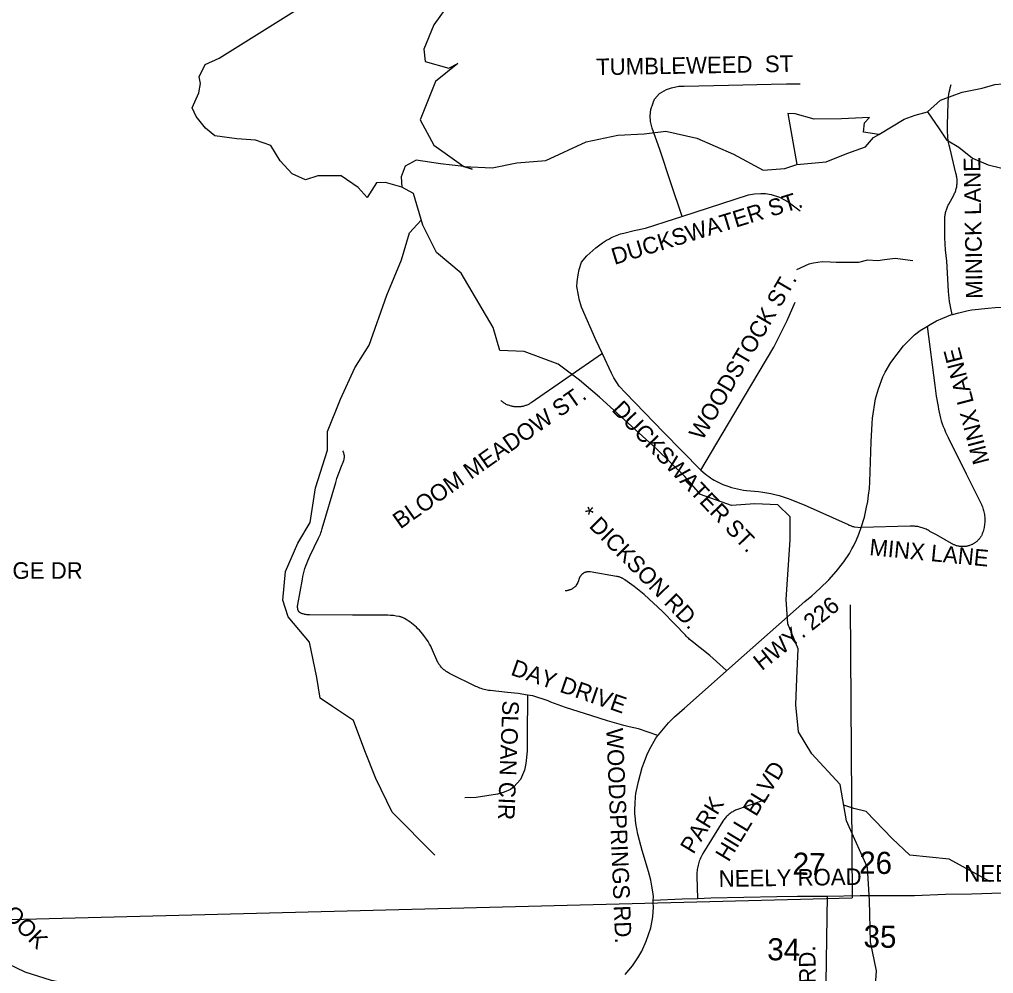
# Model space of a CAD drawing. Extents: x 1670563 to 1761545, y 515755 to 578944.
# Drawn here: x 1679340 to 1683746, y 538317 to 542631 of the extents above; entities that cross this region are included whole.
import ezdxf

# ---------------------------------------------------------------- set-up
doc = ezdxf.new("R2010")
doc.units = 0
for name, color, linetype in [('5_sectionlines', 7, 'Continuous'), ('62_text', 7, 'Continuous'), ('SHP_LINE', 7, 'Continuous'), ('STREETCL', 7, 'Continuous'), ('STRNAMES', 7, 'Continuous')]:
    doc.layers.add(name, color=color, linetype=linetype)

msp = doc.modelspace()

# ---------------------------------------------------------------- linework, layer by layer
at = {"layer": '5_sectionlines'}
for p in [(1683097.4, 539985.1), (1677796.8, 538521.9)]:
    msp.add_line(p, (1683105.9, 538659.8), dxfattribs=at)
at = {"layer": 'SHP_LINE'}
for points in [[(1681069, 541873), (1680995, 541894), (1680955, 541892), (1680913, 541826), (1680871, 541872), (1680795, 541924), (1680689, 541924), (1680633, 541906), (1680573, 541934), (1680519, 541992), (1680477, 542062), (1680407, 542086), (1680323, 542092), (1680223, 542106), (1680181, 542140), (1680139, 542192), (1680121, 542232), (1680151, 542300), (1680159, 542342), (1680153, 542372), (1680179, 542428), (1680243, 542456), (1681080, 542981)], [(1681276, 542693), (1681214, 542607), (1681168, 542497), (1681174, 542441), (1681282, 542411), (1681322, 542433), (1681222, 542351), (1681152, 542177), (1681214, 542063), (1681276, 542019), (1681350, 541966), (1681244, 541978), (1681134, 541995), (1681084, 541968), (1681066, 541920), (1681069, 541873)], [(1683447, 542214), (1683506, 542266), (1683570, 542290), (1683604, 542303), (1683694, 542321), (1683752, 542337), (1683786, 542340), (1683841, 542370), (1683875, 542429), (1683912, 542490), (1683940, 542540), (1683971, 542577), (1684011, 542613)], [(1682816, 542206), (1682856, 541976), (1682988, 541988), (1683082, 542026), (1683166, 542056), (1683203, 542098), (1683227, 542112), (1683158, 542122), (1683162, 542164), (1683184, 542188), (1683058, 542182), (1682934, 542180), (1682848, 542204), (1682816, 542206)], [(1683227, 542112), (1683342, 542180), (1683392, 542198), (1683447, 542214)], [(1683447, 542214), (1683500, 542137), (1683533, 542087), (1683589, 542054), (1683650, 542004), (1683721, 541974), (1683777, 541961), (1683838, 541955), (1683995, 541875), (1684060, 541807), (1684122, 541758), (1684211, 541718), (1684291, 541690), (1684383, 541657)], [(1681350, 541966), (1681388, 541954), (1681350, 541966), (1681478, 541961), (1681590, 541983), (1681720, 541993), (1681903, 542078), (1682047, 542108), (1682165, 542114), (1682263, 542126), (1682403, 542094), (1682570, 542022), (1682704, 541950), (1682802, 541958), (1682856, 541976)], [(1683212, 538264), (1683217, 538329), (1683189, 538460), (1683184, 538648), (1683175, 538797), (1683118, 538924), (1683080, 539008), (1683052, 539172), (1682924, 539310), (1682864, 539410), (1682852, 539532), (1682856, 539652), (1682862, 539786), (1682816, 539898), (1682808, 540009), (1682826, 540279), (1682826, 540383), (1682770, 540437), (1682666, 540441), (1682560, 540433), (1682420, 540483), (1682350, 540565), (1682222, 540689), (1681963, 540924), (1681873, 541000), (1681777, 541072), (1681623, 541130), (1681513, 541134), (1681482, 541239), (1681338, 541485), (1681226, 541577), (1681164, 541701), (1681122, 541845), (1681069, 541873)], [(1681218, 538853), (1681026, 539047), (1680952, 539199), (1680902, 539325), (1680851, 539462), (1680755, 539524), (1680699, 539562), (1680685, 539656), (1680651, 539816), (1680555, 539930), (1680531, 540005), (1680543, 540135), (1680599, 540263), (1680655, 540357), (1680679, 540513), (1680733, 540684), (1680733, 540768), (1680791, 540914), (1680857, 541056), (1680922, 541158), (1681002, 541385), (1681068, 541545), (1681104, 541667), (1681157, 541724)], [(1683380, 541540), (1683301, 541550), (1683252, 541544), (1683223, 541540), (1683176, 541543), (1683135, 541532), (1683064, 541532), (1683034, 541532), (1683007, 541534), (1682970, 541535), (1682932, 541529), (1682910, 541525), (1682855, 541500)], [(1680210, 537900), (1680101, 538009), (1679998, 538040), (1679920, 538045), (1679823, 538143), (1679747, 538185), (1679588, 538265), (1679485, 538285), (1679365, 538324), (1679245, 538380), (1679175, 538427), (1679142, 538491), (1679100, 538513), (1678966, 538458), (1678919, 538405), (1678858, 538410), (1678818, 538527), (1678699, 538692), (1678634, 538784), (1678598, 538892), (1678598, 538990), (1678608, 539076)], [(1683732, 538732), (1683545, 538835), (1683367, 538853), (1683287, 538928), (1683170, 539050), (1683114, 539064), (1683068, 539079)]]:
    msp.add_lwpolyline(points, dxfattribs=at)
at = {"layer": 'STREETCL'}
for points in [[(1682336.9, 541740.5), (1682286.6, 541892.4), (1682236.1, 542044), (1682201.5, 542140.2), (1682194.4, 542170.5), (1682193.2, 542195.3), (1682196, 542224.8), (1682205.4, 542254.7), (1682212.3, 542271), (1682235.3, 542297.1), (1682266.2, 542314.9), (1682289.5, 542322.5), (1682321.6, 542329.7), (1682346.1, 542330), (1682547.1, 542334.1), (1682739.7, 542339.1), (1682808.5, 542340.1), (1682871.2, 542340.8)], [(1683559.3, 541297.2), (1683552.8, 541326.1), (1683549.6, 541341), (1683547, 541355.9), (1683544.8, 541370.9), (1683543.2, 541386), (1683541.9, 541401.1), (1683535.8, 541512.3), (1683533.9, 541538.1), (1683531.2, 541563.9), (1683528.3, 541590.5), (1683526.3, 541617.2), (1683525, 541643.9), (1683525.8, 541731.3), (1683525.9, 541735.9), (1683526.2, 541740.4), (1683526.6, 541744.9), (1683527.2, 541749.3), (1683528, 541753.8), (1683528.8, 541758.2), (1683529.9, 541762.6), (1683531.1, 541767), (1683532.4, 541771.3), (1683533.9, 541775.6), (1683535.6, 541779.8), (1683537.3, 541783.9), (1683539.3, 541788), (1683541.3, 541792.1), (1683543.5, 541796), (1683565.9, 541837.6), (1683567.9, 541841.5), (1683569.8, 541845.5), (1683571.5, 541849.5), (1683573.1, 541853.7), (1683574.6, 541857.8), (1683575.9, 541862), (1683577.1, 541866.3), (1683578.2, 541870.6), (1683579.1, 541874.9), (1683579.8, 541879.3), (1683580.4, 541883.6), (1683580.9, 541888), (1683581.1, 541892.4), (1683581.3, 541896.9), (1683581.3, 541901.3), (1683581.1, 541905.7), (1683580.8, 541910.1), (1683580.4, 541914.5), (1683579.8, 541918.9), (1683579, 541923.2), (1683578.1, 541927.5), (1683577.1, 541931.8), (1683575.9, 541936.1), (1683547.4, 542052.2), (1683544.8, 542063.4), (1683542.7, 542074.6), (1683540.9, 542086), (1683539.5, 542097.3), (1683538.4, 542108.7), (1683537.8, 542120.2), (1683537.5, 542131.7), (1683537.6, 542143.1), (1683538.1, 542154.6), (1683540.5, 542253.9), (1683540.8, 542263.6), (1683541.5, 542273.4), (1683542.5, 542283.1), (1683543.9, 542292.8), (1683545.5, 542302.5), (1683547.4, 542312.1), (1683549.7, 542321.6), (1683554.3, 542337.4)], [(1682335.6, 541740), (1682636.7, 541838.1), (1682664.8, 541843.6), (1682692.9, 541845.2), (1682714, 541844.4), (1682740.6, 541839.7), (1682777.2, 541828), (1682816.2, 541806.1), (1682871.8, 541766)], [(1681976.7, 541119.4), (1681947.4, 541182.3), (1681881.8, 541329.8), (1681870.7, 541367.1), (1681868.4, 541384.2), (1681861.4, 541423.3), (1681862.2, 541445.1), (1681866.1, 541476.3), (1681871.5, 541501.3), (1681882.5, 541533.3), (1681905.3, 541562.7), (1681946.8, 541598.9), (1681977.6, 541621), (1681986.5, 541627.1), (1681995.5, 541632.9), (1682004.8, 541638.4), (1682014.2, 541643.7), (1682021.3, 541647.3), (1682028.6, 541650.7), (1682035.9, 541653.8), (1682043.3, 541656.7), (1682050.9, 541659.3), (1682058.5, 541661.7), (1682066.2, 541663.8), (1682073.9, 541665.6), (1682120.6, 541677), (1682171.9, 541688), (1682302.6, 541729.3), (1682335.6, 541740)], [(1682421.2, 540593.8), (1682619.2, 540926.7), (1682752.2, 541149.9), (1682812, 541269.5), (1682848.9, 541352.9)], [(1683560.3, 541297.5), (1683588.5, 541305.2), (1683631.7, 541315.5), (1683646.9, 541318.3), (1683721.4, 541326.5), (1683753.7, 541328.9), (1683813.5, 541332.3), (1683871.5, 541335), (1683938.4, 541337.6), (1684052.2, 541342.8), (1684091.8, 541345.5), (1684131.3, 541349.3)], [(1683446.9, 541245.2), (1683458.7, 541252.4), (1683487.2, 541268.9), (1683516.6, 541281), (1683551.9, 541295.2), (1683560.3, 541297.5)], [(1683147.1, 540334.1), (1683161.5, 540380.3), (1683171.7, 540426.6), (1683177.1, 540451.5), (1683180.6, 540480.5), (1683184.3, 540509.9), (1683186.1, 540541.1), (1683192.3, 540721), (1683196.8, 540804.8), (1683199, 540827.9), (1683211.5, 540915.7), (1683224.9, 540961.1), (1683245, 541015), (1683256.1, 541036), (1683281.1, 541079.6), (1683338.6, 541155.4), (1683366.6, 541184.3), (1683388.5, 541204.8), (1683414.1, 541224.8), (1683446.9, 541245.2)], [(1683445.3, 541244.2), (1683480.7, 540975.7), (1683487, 540928.7), (1683494.9, 540881.9), (1683496.9, 540868.6), (1683499.4, 540855.3), (1683502.3, 540842.1), (1683505.6, 540829), (1683509.4, 540816.1), (1683513.7, 540803.2), (1683518.4, 540790.6), (1683523.5, 540778.1), (1683529, 540765.7), (1683535, 540753.6), (1683541.3, 540741.7), (1683622.6, 540577.4), (1683688.5, 540443.7), (1683691, 540438.4), (1683693.4, 540432.9), (1683695.5, 540427.3), (1683697.5, 540421.7), (1683699.3, 540416), (1683700.8, 540410.3), (1683702.2, 540404.5), (1683703.4, 540398.6), (1683704.4, 540392.8), (1683705.2, 540386.8), (1683705.7, 540380.9), (1683706.1, 540375), (1683706.3, 540369), (1683706.2, 540363.1), (1683706, 540357.1), (1683705.5, 540351.2), (1683704.8, 540345.2), (1683704, 540339.3), (1683702.9, 540333.5), (1683701.6, 540327.7), (1683700.2, 540321.9), (1683698.5, 540316.2), (1683696.6, 540310.5), (1683694.6, 540304.9), (1683692.3, 540299.4), (1683690.7, 540296.5), (1683689, 540293.6), (1683687.2, 540290.8), (1683685.3, 540288.1), (1683683.3, 540285.4), (1683681.2, 540282.8), (1683679.1, 540280.2), (1683676.8, 540277.8), (1683674.5, 540275.4), (1683672, 540273.1), (1683669.5, 540270.9), (1683667, 540268.8), (1683664.3, 540266.8), (1683661.6, 540264.8), (1683658.8, 540263), (1683656, 540261.2), (1683653.1, 540259.6), (1683650.1, 540258), (1683647.1, 540256.6), (1683644.1, 540255.2), (1683641, 540254), (1683637.8, 540252.9), (1683634.7, 540251.8), (1683631.5, 540250.9), (1683628.2, 540250.1), (1683625, 540249.4), (1683621.7, 540248.9), (1683618.4, 540248.4), (1683615.1, 540248), (1683611.7, 540247.8), (1683608.4, 540247.7), (1683605.1, 540247.7), (1683601.7, 540247.8), (1683598.4, 540248), (1683595.1, 540248.4), (1683591.8, 540248.8), (1683588.5, 540249.4), (1683585.2, 540250), (1683582, 540250.8), (1683578.8, 540251.7), (1683575.6, 540252.7), (1683572.4, 540253.9), (1683569.3, 540255.1), (1683566.3, 540256.4), (1683487.7, 540300.4), (1683458.1, 540316.2), (1683453.9, 540318.9), (1683449.7, 540321.5), (1683445.3, 540323.9), (1683440.9, 540326.1), (1683436.3, 540328.2), (1683431.7, 540330.1), (1683427.1, 540331.8), (1683422.4, 540333.4), (1683417.6, 540334.8), (1683412.8, 540336.1), (1683407.9, 540337.2), (1683403, 540338.1), (1683398.1, 540338.8), (1683393.2, 540339.4), (1683388.2, 540339.8), (1683383.2, 540340), (1683378.3, 540340.1), (1683373.3, 540340), (1683368.3, 540339.7), (1683147.1, 540334.1)], [(1681976.2, 541120.4), (1681654.2, 540898.2), (1681651.1, 540896.2), (1681648, 540894.3), (1681644.9, 540892.5), (1681641.7, 540890.8), (1681638.4, 540889.2), (1681635.1, 540887.7), (1681631.7, 540886.3), (1681628.3, 540885.1), (1681624.8, 540883.9), (1681621.3, 540882.9), (1681617.8, 540882), (1681614.2, 540881.2), (1681610.6, 540880.6), (1681607, 540880), (1681603.4, 540879.6), (1681599.8, 540879.3), (1681596.2, 540879.1), (1681592.5, 540879.1), (1681588.9, 540879.2), (1681585.2, 540879.4), (1681581.6, 540879.7), (1681577.8, 540880.1), (1681574.1, 540880.6), (1681570.4, 540881.3), (1681566.7, 540882.1), (1681563, 540883), (1681559.3, 540884.1), (1681555.7, 540885.3), (1681552.2, 540886.6), (1681548.7, 540888), (1681545.2, 540889.5), (1681541.8, 540891.1), (1681538.4, 540892.9), (1681535.1, 540894.8), (1681531.9, 540896.8), (1681528.8, 540898.9), (1681525.7, 540901.1), (1681522.7, 540903.4), (1681519.7, 540905.8), (1681516.9, 540908.3)], [(1682421.2, 540593.8), (1682252.1, 540765.4), (1682081.1, 540942.8), (1682052.2, 540974), (1682028.8, 541011.5), (1682017.1, 541032.6), (1681976.7, 541119.4)], [(1681637.3, 539576.7), (1681596.1, 539583.7), (1681546.6, 539588.3), (1681468.7, 539596.8), (1681461.9, 539597.7), (1681455.2, 539598.8), (1681448.5, 539600.2), (1681441.8, 539601.8), (1681435.2, 539603.6), (1681428.7, 539605.6), (1681422.2, 539607.9), (1681415.8, 539610.3), (1681409.5, 539613), (1681403.3, 539615.9), (1681288.4, 539672.7), (1681284.6, 539674.6), (1681280.8, 539676.6), (1681277.1, 539678.7), (1681273.4, 539680.9), (1681269.9, 539683.3), (1681266.4, 539685.8), (1681263, 539688.4), (1681259.7, 539691.2), (1681256.5, 539694), (1681253.4, 539696.9), (1681250.4, 539700), (1681247.5, 539703.2), (1681244.7, 539706.4), (1681242, 539709.7), (1681239.5, 539713.2), (1681237, 539716.7), (1681234.7, 539720.3), (1681232.5, 539724), (1681203.8, 539789.3), (1681201.8, 539793.8), (1681199.6, 539798.2), (1681197.3, 539802.6), (1681194.9, 539806.8), (1681187.7, 539818.3), (1681180.1, 539829.6), (1681172.2, 539840.6), (1681164, 539851.4), (1681155.4, 539862), (1681148.9, 539869.2), (1681142.2, 539876.1), (1681135.3, 539882.8), (1681128.1, 539889.3), (1681120.7, 539895.6), (1681113.1, 539901.6), (1681105.3, 539907.3), (1681097.4, 539912.8), (1681089.2, 539918), (1681080.9, 539923), (1681078.3, 539924.3), (1681075.5, 539925.6), (1681072.8, 539926.8), (1681070, 539927.9), (1681067.2, 539928.9), (1681064.3, 539929.8), (1681061.4, 539930.6), (1681058.5, 539931.3), (1681055.6, 539931.8), (1681043.3, 539933.9), (1681030.9, 539935.5), (1681018.5, 539936.7), (1681006.1, 539937.4), (1680993.6, 539937.7), (1680846.7, 539937.4), (1680651.8, 539938.6), (1680647.6, 539938.8), (1680643.4, 539939.2), (1680639.2, 539939.7), (1680635, 539940.4), (1680630.8, 539941.2), (1680626.7, 539942.1), (1680622.6, 539943.2), (1680618.6, 539944.5), (1680614.6, 539945.8), (1680613.8, 539946.1), (1680613.1, 539946.4), (1680612.3, 539946.8), (1680611.6, 539947.1), (1680610.8, 539947.5), (1680610.1, 539947.9), (1680609.4, 539948.4), (1680608.7, 539948.8), (1680608, 539949.3), (1680607.4, 539949.8), (1680606.8, 539950.4), (1680606.1, 539950.9), (1680605.5, 539951.5), (1680605, 539952.1), (1680604.4, 539952.7), (1680603.9, 539953.3), (1680603.3, 539954), (1680602.8, 539954.6), (1680602.4, 539955.3), (1680601.9, 539956), (1680601.5, 539956.7), (1680601.1, 539957.5), (1680600.7, 539958.2), (1680600.4, 539958.9), (1680600, 539959.7), (1680599.7, 539960.5), (1680599.5, 539961.3), (1680599.2, 539962.1), (1680598.8, 539964.4), (1680598.4, 539966.8), (1680598.1, 539969.1), (1680597.9, 539971.5), (1680597.8, 539973.9), (1680597.7, 539976.3), (1680597.8, 539978.6), (1680597.9, 539981), (1680598.1, 539983.4), (1680598.3, 539985.8), (1680619.3, 540100.9), (1680621.6, 540112.9), (1680624.3, 540124.9), (1680627.4, 540136.7), (1680630.8, 540148.5), (1680634.6, 540160.1), (1680638.8, 540171.6), (1680643.4, 540183), (1680648.3, 540194.2), (1680653.5, 540205.2), (1680692.4, 540286.3), (1680695.4, 540292.2), (1680698.2, 540298.2), (1680700.8, 540304.4), (1680703.2, 540310.6), (1680705.4, 540316.9), (1680707.4, 540323.3), (1680709.1, 540329.7), (1680770.4, 540538.3), (1680775.2, 540555), (1680780.6, 540571.6), (1680786.6, 540587.9), (1680793.1, 540604), (1680806.6, 540637.5), (1680807.2, 540639.2), (1680807.6, 540641), (1680808.1, 540642.8), (1680808.4, 540644.6), (1680808.7, 540646.4), (1680809, 540648.2), (1680809.1, 540650.1), (1680809.3, 540651.9), (1680809.3, 540653.7), (1680809.3, 540655.6), (1680809.2, 540657.4), (1680809.1, 540659.2), (1680808.9, 540661.1), (1680808.6, 540662.9), (1680808.3, 540664.7), (1680807.9, 540666.5), (1680807.5, 540668.3), (1680807, 540670), (1680806.4, 540671.8), (1680805.8, 540673.5), (1680805.1, 540675.2), (1680804.4, 540676.9), (1680803.6, 540678.6), (1680802.8, 540680.2)], [(1682421.2, 540593.8), (1682441.8, 540576.6), (1682449.6, 540570.4), (1682457.5, 540564.4), (1682465.7, 540558.7), (1682474, 540553.3), (1682482.5, 540548.2), (1682491.2, 540543.4), (1682500.1, 540538.9), (1682509.1, 540534.7), (1682521.8, 540529.3), (1682534.8, 540524.3), (1682547.9, 540519.8), (1682561.1, 540515.6), (1682574.5, 540512), (1682588, 540508.7), (1682601.6, 540506), (1682615.2, 540503.6), (1682629, 540501.8), (1682663.9, 540498), (1682682.7, 540496.3), (1682701.5, 540494), (1682720.2, 540491.1), (1682738.8, 540487.5), (1682757.2, 540483.4), (1682775.6, 540478.6), (1682793.7, 540473.2), (1682811.7, 540467.3), (1682829.4, 540460.7), (1682846.9, 540453.6), (1682889.7, 540436.1), (1683088, 540347), (1683091.3, 540345.4), (1683094.6, 540344), (1683098, 540342.6), (1683101.4, 540341.4), (1683104.9, 540340.2), (1683108.4, 540339.2), (1683111.9, 540338.3), (1683115.5, 540337.5), (1683147.1, 540334.1)], [(1682227.2, 539393), (1682229.6, 539396.2), (1682275.5, 539451), (1682302.2, 539477.8), (1682347.2, 539517.9), (1682617.2, 539757.1), (1682892.6, 539998.9), (1682923.3, 540025.2), (1682962, 540060), (1683001.3, 540097.4), (1683034.2, 540134.8), (1683069, 540178.9), (1683093.5, 540217.2), (1683105.1, 540237.3), (1683111.6, 540249.3), (1683125.8, 540277.8), (1683136.5, 540304.1), (1683147.1, 540334.1)], [(1682538.3, 539687.2), (1682461.8, 539755.1), (1682374.9, 539824.8), (1682370.9, 539828.1), (1682367, 539831.5), (1682363.2, 539835.1), (1682359.6, 539838.8), (1682356.1, 539842.6), (1682352.8, 539846.6), (1682304.7, 539897.5), (1682247.8, 539954.4), (1682166.1, 540031.5), (1682120.7, 540067.9), (1682078.2, 540097.4), (1682076.1, 540099), (1682074, 540100.5), (1682071.8, 540101.9), (1682069.6, 540103.2), (1682067.3, 540104.5), (1682065, 540105.7), (1682062.6, 540106.8), (1682060.2, 540107.9), (1682057.8, 540108.8), (1682055.3, 540109.7), (1682052.9, 540110.5), (1682050.3, 540111.2), (1682047.8, 540111.8), (1682045.3, 540112.4), (1682042.7, 540112.8), (1682040.1, 540113.2), (1681921.7, 540134), (1681920, 540134.1), (1681918.4, 540134.3), (1681916.8, 540134.3), (1681915.1, 540134.3), (1681913.5, 540134.3), (1681911.8, 540134.2), (1681910.2, 540134), (1681908.6, 540133.8), (1681907, 540133.5), (1681905.4, 540133.2), (1681903.8, 540132.8), (1681902.2, 540132.4), (1681900.6, 540131.9), (1681899.1, 540131.3), (1681897.6, 540130.7), (1681896.1, 540130.1), (1681894.6, 540129.4), (1681893.1, 540128.6), (1681891.7, 540127.8), (1681890.3, 540127), (1681888.9, 540126.1), (1681887.6, 540125.1), (1681886.3, 540124.1), (1681885, 540123.1), (1681883.8, 540122), (1681882.6, 540120.9), (1681881.4, 540119.7), (1681880.3, 540118.5), (1681879.3, 540117.3), (1681878.2, 540116), (1681877.3, 540114.7), (1681876.3, 540113.3), (1681875.4, 540111.9), (1681874.6, 540110.5), (1681873.8, 540109.1), (1681873.1, 540107.6), (1681872.4, 540106.1), (1681871.7, 540104.6), (1681871.1, 540103.1), (1681870.6, 540101.6), (1681870.1, 540100), (1681867.7, 540093.6), (1681864.7, 540086), (1681861.5, 540078.4), (1681854, 540066.9), (1681852.1, 540065.2), (1681850.2, 540063.6), (1681848.2, 540062.1), (1681846.1, 540060.6), (1681844, 540059.2), (1681841.9, 540057.9), (1681839.7, 540056.7), (1681837.5, 540055.5), (1681835.3, 540054.4), (1681833, 540053.4), (1681830.6, 540052.4), (1681828.3, 540051.6), (1681825.9, 540050.8), (1681823.5, 540050.1), (1681821.1, 540049.5), (1681818.6, 540048.9), (1681816.2, 540048.5), (1681813.7, 540048.1), (1681811.2, 540047.8), (1681808.7, 540047.6)], [(1681637.3, 539576.7), (1681636.3, 539390.4), (1681635.4, 539323.5), (1681630.3, 539267.7), (1681624.1, 539236.6), (1681605.5, 539194), (1681575.5, 539161.3), (1681560.2, 539150), (1681531.7, 539136.8), (1681501.5, 539127.8), (1681404.8, 539113.8), (1681353.4, 539111.6)], [(1682227.2, 539393), (1682139.8, 539423), (1682097.3, 539432.7), (1682074, 539438.9), (1681999.5, 539460.3), (1681928, 539483.2), (1681809.7, 539519.7), (1681742.8, 539544.8), (1681731.5, 539550.3), (1681662.4, 539572.4), (1681637.3, 539576.7)], [(1682206.7, 538648.7), (1682206.9, 538664.8), (1682205.6, 538677.7), (1682200.3, 538711.6), (1682195.4, 538739.6), (1682185.5, 538778.8), (1682181.1, 538793.1), (1682156.9, 538873.3), (1682144, 538919.1), (1682136.9, 538947.7), (1682128.4, 538996.2), (1682124.4, 539030.5), (1682123.5, 539037.6), (1682123, 539056.8), (1682124.4, 539086.6), (1682126.6, 539116.9), (1682128.4, 539131.2), (1682139.1, 539185.5), (1682156.9, 539249.2), (1682166.7, 539275.5), (1682177.5, 539304.5), (1682189.9, 539330.3), (1682218.5, 539381.1), (1682227.2, 539393)], [(1682720.8, 539106), (1682591.5, 539061), (1682587.1, 539059.4), (1682582.7, 539057.6), (1682578.4, 539055.6), (1682574.2, 539053.6), (1682570, 539051.3), (1682565.9, 539049), (1682561.9, 539046.5), (1682558, 539043.8), (1682554.1, 539041), (1682550.4, 539038.1), (1682546.8, 539035.1), (1682543.3, 539031.9), (1682539.9, 539028.7), (1682536.6, 539025.3), (1682533.4, 539021.8), (1682530.3, 539018.2), (1682527.4, 539014.4), (1682524.6, 539010.6), (1682521.9, 539006.7), (1682431.1, 538859.3), (1682427.8, 538853.8), (1682424.8, 538848.2), (1682421.9, 538842.6), (1682419.3, 538836.8), (1682416.8, 538830.9), (1682414.6, 538824.9), (1682412.5, 538818.9), (1682410.7, 538812.8), (1682409.1, 538806.6), (1682407.7, 538800.4), (1682406.5, 538794.1), (1682405.6, 538787.8), (1682404.9, 538781.5), (1682404.3, 538775.2), (1682404.1, 538768.8), (1682404, 538762.4), (1682404.1, 538756.1), (1682406.3, 538656.7)], [(1682206.7, 538648.7), (1682337.8, 538654.3), (1682406.3, 538656.7)], [(1682406.3, 538656.7), (1682467.3, 538658.8), (1682765.8, 538665.6), (1682859.4, 538666.6), (1682992.5, 538667.8), (1682993.4, 538667.8)], [(1682993.4, 538667.8), (1682990.2, 538476.3), (1682987.8, 538273.8), (1682985.5, 538015), (1682984.6, 537755.7), (1682979.6, 537517.9)], [(1682993.4, 538667.8), (1683141.8, 538670.2), (1683252.6, 538670.7), (1683388.7, 538670.6), (1683529, 538676), (1683645.4, 538678), (1683784.6, 538682.4), (1683952.7, 538686.6), (1684117.4, 538689), (1684332.9, 538692.3), (1684474.9, 538696.5), (1684492.4, 538697.4)], [(1682078.8, 538313.5), (1682112.5, 538351.7), (1682136.9, 538388.2), (1682154.3, 538418.8), (1682174.1, 538462.9), (1682194.8, 538523.2), (1682203.9, 538573.7), (1682207.4, 538618), (1682206.5, 538638.1), (1682206.7, 538648.7)]]:
    msp.add_lwpolyline(points, dxfattribs=at)

# ---------------------------------------------------------------- texts
at = {"layer": '62_text'}
for s, rotation, p in [('27', 358.644, (1682835.6, 538764.7)), ('26', 359.2136, (1683137.4, 538769.2)), ('35', 358.9328, (1683157, 538435.5)), ('34', 358.932, (1682721.5, 538377.7))]:
    msp.add_text(s, height=100, rotation=rotation, dxfattribs=at).set_placement(p)
at = {"layer": 'STRNAMES'}
for s, rotation, p in [('TUMBLEWEED  ST', 1, (1681948.7, 542379.2)), ('MINICK LANE', 90.9896, (1683696.5, 541368.9)), ('DUCKSWATER ST.', 17.0725, (1682031, 541521.2)), ('WOODSTOCK ST.', 59.6729, (1682428.6, 540723.6)), ('MINX LANE', 104.6907, (1683728, 540630.7)), ('BLOOM MEADOW ST.', 35.028, (1681062.2, 540325.2)), ('DUCKSWATER ST.', 313.653, (1682015, 540864)), ('* DICKSON RD. ', 314.3613, (1681865.5, 540386)), ('MINX LANE', 354.4555, (1683182, 540209.4)), ('HWY. 226', 38.5069, (1682697.4, 539684.1)), ('DAY DRIVE', 340.8514, (1681557.8, 539669)), ('SLOAN CIR', 267.7542, (1681524.7, 539553)), ('WOODSPRINGS RD.', 272.4044, (1681993.8, 539425.5)), ('HILL BLVD', 58.7757, (1682547.3, 538818.2)), ('PARK', 58.7757, (1682388.2, 538853.2)), ('INNISBROOK', 314.9807, (1678976, 538867.7)), ('NEELY ROAD', 0.8296, (1682503, 538708.8)), ('NEELY RD.', 359.9529, (1683613.6, 538732.5)), ('ROSELEE RD.', 90.7196, (1682948.2, 537770.2))]:
    msp.add_text(s, height=75, rotation=rotation, dxfattribs=at).set_placement(p)
msp.add_text('VINTAGE DR', height=75, dxfattribs=at).set_placement((1679012.6, 540102.1))

doc.saveas('drawing.dxf')
